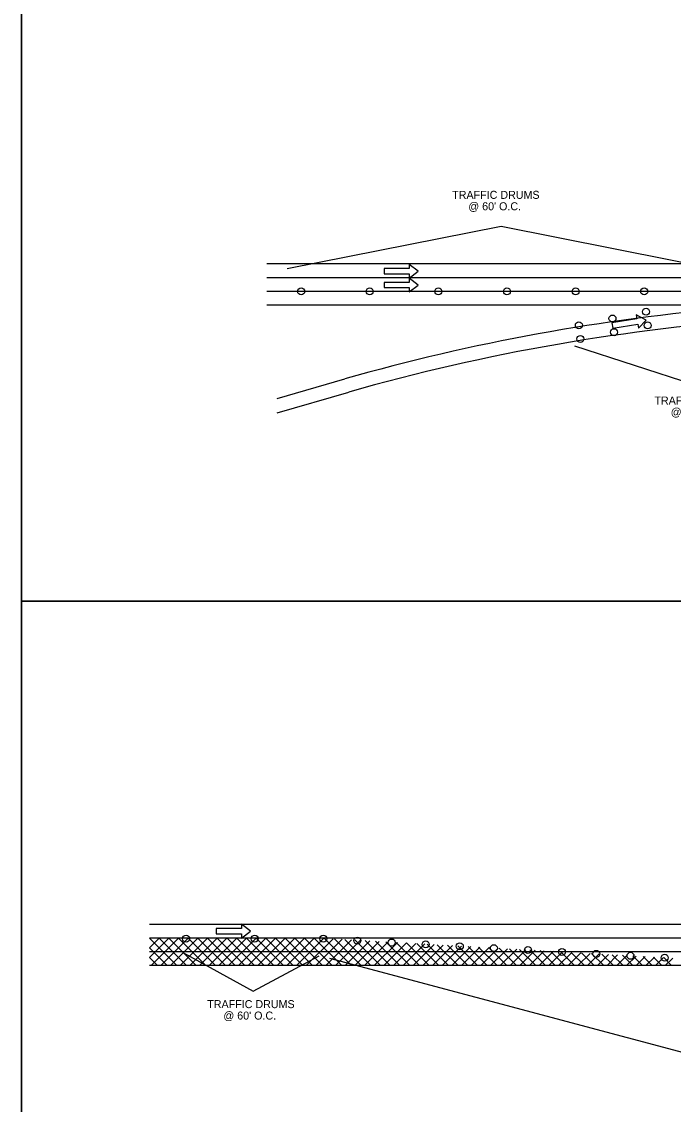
# Model space of a CAD drawing. Extents: x -100 to 745, y -1581 to -107.
# Drawn here: x 175.4 to 232.4, y -1294.6 to -1199.9 of the extents above; entities that cross this region are included whole.
import ezdxf

# ---------------------------------------------------------------- set-up
doc = ezdxf.new("R2010")
doc.units = 0
for name, color, linetype in [('Default', 7, 'Continuous'), ('R_Contour Annot', 7, 'Continuous'), ('R_Draft', 7, 'Continuous'), ('R_Drive', 7, 'Continuous'), ('R_Erosion', 7, 'Continuous')]:
    doc.layers.add(name, color=color, linetype=linetype)

msp = doc.modelspace()

# ---------------------------------------------------------------- linework, layer by layer
at = {"layer": 'Default'}
for points in [[(209.301, -1222.326), (210.08, -1221.726), (209.301, -1221.126), (209.301, -1221.501), (207.095, -1221.501), (207.095, -1221.951), (209.301, -1221.951)], [(209.301, -1223.535), (210.08, -1222.935), (209.301, -1222.335), (209.301, -1222.71), (207.095, -1222.71), (207.095, -1223.16), (209.301, -1223.16)], [(229.342, -1226.717), (230.017, -1226.002), (229.153, -1225.532), (229.212, -1225.902), (227.033, -1226.249), (227.104, -1226.693), (229.283, -1226.346)], [(194.636, -1280.026), (195.415, -1279.426), (194.636, -1278.826), (194.636, -1279.201), (192.43, -1279.201), (192.43, -1279.651), (194.636, -1279.651)]]:
    msp.add_lwpolyline(points, close=True, dxfattribs=at)
at = {"layer": 'R_Contour Annot'}
for points in [[(175.406, -1140.582), (345.406, -1140.582), (345.406, -1250.582), (175.406, -1250.582)], [(175.406, -1250.582), (345.406, -1250.582), (345.406, -1360.582), (175.406, -1360.582)]]:
    msp.add_lwpolyline(points, close=True, dxfattribs=at)
at = {"layer": 'R_Draft'}
for p, q in [((326.815, -1221.09), (196.834, -1221.09)), ((326.815, -1222.29), (196.834, -1222.29)), ((326.815, -1223.49), (196.834, -1223.49)), ((237.745, -1224.69), (196.834, -1224.69)), ((197.745, -1232.849), (203.679, -1231.136)), ((197.745, -1234.098), (204.01, -1232.29)), ((325.145, -1278.839), (186.576, -1278.836)), ((325.145, -1280.039), (186.576, -1280.036)), ((186.576, -1281.733), (188.273, -1280.036)), ((186.576, -1280.884), (187.424, -1280.036)), ((186.576, -1280.036), (188.976, -1282.436)), ((186.721, -1282.436), (189.121, -1280.036)), ((187.424, -1280.036), (189.824, -1282.436)), ((187.57, -1282.436), (189.97, -1280.036)), ((188.273, -1280.036), (190.673, -1282.436)), ((188.418, -1282.436), (190.818, -1280.036)), ((189.122, -1280.036), (191.521, -1282.436)), ((189.267, -1282.436), (191.666, -1280.036)), ((189.97, -1280.036), (192.37, -1282.436)), ((190.115, -1282.436), (192.515, -1280.036)), ((190.819, -1280.036), (193.219, -1282.436)), ((190.964, -1282.436), (193.363, -1280.036)), ((191.667, -1280.036), (194.067, -1282.436)), ((191.812, -1282.436), (194.212, -1280.037)), ((192.516, -1280.036), (194.916, -1282.436)), ((192.661, -1282.436), (195.06, -1280.037)), ((193.365, -1280.036), (195.764, -1282.436)), ((193.509, -1282.436), (195.909, -1280.037)), ((194.213, -1280.037), (196.613, -1282.436)), ((194.358, -1282.436), (196.757, -1280.037)), ((195.062, -1280.037), (197.461, -1282.436)), ((195.206, -1282.436), (197.606, -1280.037)), ((195.91, -1280.037), (198.31, -1282.436)), ((196.055, -1282.436), (198.454, -1280.037)), ((196.759, -1280.037), (199.158, -1282.436)), ((196.903, -1282.436), (199.302, -1280.037)), ((197.608, -1280.037), (200.007, -1282.436)), ((197.752, -1282.436), (200.151, -1280.037)), ((198.456, -1280.037), (200.855, -1282.436)), ((198.6, -1282.436), (200.999, -1280.037)), ((199.305, -1280.037), (201.704, -1282.436)), ((199.449, -1282.436), (201.842, -1280.043)), ((200.154, -1280.037), (202.553, -1282.436)), ((200.298, -1282.436), (202.644, -1280.089)), ((201.002, -1280.037), (203.401, -1282.436)), ((201.146, -1282.436), (203.447, -1280.135)), ((201.858, -1280.044), (204.25, -1282.436)), ((201.995, -1282.436), (204.25, -1280.181)), ((202.758, -1280.096), (205.098, -1282.436)), ((202.843, -1282.436), (205.053, -1280.227)), ((203.658, -1280.147), (205.947, -1282.436)), ((203.692, -1282.436), (205.855, -1280.272)), ((204.54, -1282.436), (206.658, -1280.318)), ((204.557, -1280.198), (206.795, -1282.436)), ((205.389, -1282.436), (207.461, -1280.364)), ((205.457, -1280.25), (207.644, -1282.436)), ((206.237, -1282.436), (208.263, -1280.41)), ((206.357, -1280.301), (208.492, -1282.436)), ((207.086, -1282.436), (209.066, -1280.456)), ((207.257, -1280.352), (209.341, -1282.436)), ((207.934, -1282.436), (209.869, -1280.501)), ((208.157, -1280.404), (210.189, -1282.436)), ((208.783, -1282.436), (210.672, -1280.547)), ((209.057, -1280.455), (211.038, -1282.436)), ((209.631, -1282.436), (211.474, -1280.593)), ((209.957, -1280.506), (211.887, -1282.436)), ((210.48, -1282.436), (212.277, -1280.639)), ((210.857, -1280.558), (212.735, -1282.436)), ((211.328, -1282.436), (213.08, -1280.685)), ((211.756, -1280.609), (213.584, -1282.436)), ((212.177, -1282.436), (213.883, -1280.73)), ((212.656, -1280.66), (214.432, -1282.436)), ((213.556, -1280.712), (215.281, -1282.436)), ((214.456, -1280.763), (216.129, -1282.436)), ((186.576, -1280.884), (188.127, -1282.436)), ((325.145, -1281.239), (186.576, -1281.236)), ((213.025, -1282.436), (214.685, -1280.776)), ((213.874, -1282.436), (215.488, -1280.822)), ((214.722, -1282.436), (216.291, -1280.868)), ((215.356, -1280.815), (216.978, -1282.436)), ((215.571, -1282.436), (217.093, -1280.914)), ((216.256, -1280.866), (217.826, -1282.436)), ((216.419, -1282.436), (217.896, -1280.959)), ((217.156, -1280.917), (218.675, -1282.437)), ((217.268, -1282.436), (218.699, -1281.005)), ((218.056, -1280.969), (219.524, -1282.437)), ((218.116, -1282.436), (219.502, -1281.051)), ((218.955, -1281.02), (220.372, -1282.437)), ((218.965, -1282.437), (220.304, -1281.097)), ((219.813, -1282.437), (221.107, -1281.143)), ((219.855, -1281.071), (221.221, -1282.437)), ((220.662, -1282.437), (221.91, -1281.188)), ((220.755, -1281.123), (222.069, -1282.437)), ((221.51, -1282.437), (222.713, -1281.234)), ((221.655, -1281.174), (222.918, -1282.437)), ((222.359, -1282.437), (223.515, -1281.28)), ((222.555, -1281.225), (223.766, -1282.437)), ((223.207, -1282.437), (224.318, -1281.326)), ((223.455, -1281.277), (224.615, -1282.437)), ((224.056, -1282.437), (225.121, -1281.372)), ((224.355, -1281.328), (225.463, -1282.437)), ((224.904, -1282.437), (225.923, -1281.417)), ((225.255, -1281.379), (226.312, -1282.437)), ((225.753, -1282.437), (226.726, -1281.463)), ((226.154, -1281.431), (227.16, -1282.437)), ((226.601, -1282.437), (227.529, -1281.509)), ((227.054, -1281.482), (228.009, -1282.437)), ((227.45, -1282.437), (228.332, -1281.555)), ((227.954, -1281.533), (228.858, -1282.437)), ((228.298, -1282.437), (229.134, -1281.601)), ((228.854, -1281.585), (229.706, -1282.437)), ((229.147, -1282.437), (229.937, -1281.646)), ((229.754, -1281.636), (230.555, -1282.437)), ((229.995, -1282.437), (230.74, -1281.692)), ((230.654, -1281.687), (231.403, -1282.437)), ((186.576, -1281.733), (187.279, -1282.436)), ((243.793, -1282.437), (186.576, -1282.436)), ((230.844, -1282.437), (231.543, -1281.738)), ((231.554, -1281.739), (232.252, -1282.437)), ((231.692, -1282.437), (232.345, -1281.784))]:
    msp.add_line(p, q, dxfattribs=at)
for points in [[(175.406, -1140.582), (175.406, -1250.582), (345.406, -1250.582), (345.406, -1140.582)], [(175.406, -1250.582), (175.406, -1360.582), (345.406, -1360.582), (345.406, -1250.582)]]:
    msp.add_lwpolyline(points, close=True, dxfattribs=at)
for radius, start, end in [(180.061, 94.81769, 105.85707), (178.861, 93.85902, 105.85626)]:
    msp.add_arc((252.879, -1404.345), radius, start, end, dxfattribs=at)
at = {"layer": 'R_Drive'}
for points in [[(198.631, -1221.481), (217.344, -1217.779), (237.144, -1221.731)], [(223.752, -1228.25), (234.179, -1231.635), (237.465, -1225.454)], [(189.566, -1281.333), (195.644, -1284.664), (201.431, -1281.581)], [(202.317, -1281.776), (241.172, -1292.128), (288.54, -1287.494)]]:
    msp.add_lwpolyline(points, dxfattribs=at)
at = {"layer": 'R_Erosion'}
for centre in [(199.849, -1223.488), (205.849, -1223.488), (211.849, -1223.488), (217.849, -1223.488), (223.849, -1223.488), (229.849, -1223.488), (227.076, -1225.859), (230.016, -1225.265), (224.135, -1226.452), (227.21, -1227.056), (230.15, -1226.463), (224.269, -1227.649), (189.79, -1280.083), (195.79, -1280.083), (201.79, -1280.083), (204.769, -1280.248), (207.764, -1280.418), (210.744, -1280.582), (213.723, -1280.747), (216.702, -1280.912), (219.682, -1281.077), (222.661, -1281.241), (225.656, -1281.411), (228.651, -1281.58), (231.647, -1281.75)]:
    msp.add_circle(centre, 0.305, dxfattribs=at)

# ---------------------------------------------------------------- texts
at = {"layer": 'R_Drive'}
for s, p in [('TRAFFIC DRUMS', (213.057, -1215.398)), ("@ 60' O.C.", (214.468, -1216.398)), ('TRAFFIC DRUMS', (230.743, -1233.382)), ("@ 30' O.C.", (232.171, -1234.382)), ('TRAFFIC DRUMS', (191.637, -1286.155)), ("@ 60' O.C.", (193.048, -1287.155))]:
    msp.add_text(s, height=0.7, rotation=360, dxfattribs=at).set_placement(p)

doc.saveas('drawing.dxf')
